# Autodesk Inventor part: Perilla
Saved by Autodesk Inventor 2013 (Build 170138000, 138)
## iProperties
Created: 2013-03
Part Number: Perilla
Material: Generic
Document SubType Name: Modeling
Designer: julian.chica
Density: 1 g/cm^3
Author: julian.chica
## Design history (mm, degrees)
derived "Parlante_INICIAL.ipt"
feature "Perilla::Parlante_INICIAL.ipt" dims "d0" = 10
tag "TaggingFeature1"
body "Solid1"
